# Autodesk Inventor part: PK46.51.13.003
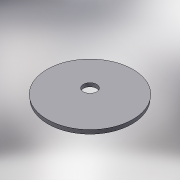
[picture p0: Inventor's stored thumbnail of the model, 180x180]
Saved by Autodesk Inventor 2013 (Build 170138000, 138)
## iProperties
Created: 2005-04
Part Number: PK46.51.13.003
Material: Stainless Steel, 440C
Document SubType Name: Sheet Metal
Designer: =<Author>
Manufacturer: Standard
Standards Organization: Custom
Description: washer
Density: 7.75 g/cm^3
Sheet Metal Rule: Default
Mass: 87.267 g
Surface Area: 82.7024 cm^2
Volume: 11.2603 cm^3
Author: PVitaliy
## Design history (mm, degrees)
node "Грань1"
body "Solid1"
sketch "Эскиз1"
  geometry: C1 r 35 at (0, 0); C2 r 5.5 at (0, 0)
  constraints: 2 centre point, 1 coincident, 1 other
  dimensions: "d0" = 70 diameter of C1; "d1" = 11 diameter of C2
feature "Плакирование1" dims "Thickness" = 3
other parameters: "BendRadius" = 3 (= Thickness), "BendReliefWidth" = 3 (= Thickness), "BendReliefDepth" = 1.5 (= 0.5 x Thickness), "CornerReliefSize" = 12 (= 4 x Thickness), "SeamGap" = 0.01, "MinimumRemnant" = 6 (= 2 x Thickness), "TransitionRadius" = 3 (= BendRadius), "d2" = 3 (= BendRadius), "JacobiRadiusSize" = 3 (= Thickness), "GapSize" = 3 (= Thickness)
